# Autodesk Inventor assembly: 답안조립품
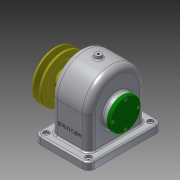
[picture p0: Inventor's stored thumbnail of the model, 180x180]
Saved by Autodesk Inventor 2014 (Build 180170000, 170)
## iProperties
Created: 2016-10
Part Number: 답안조립품
Document SubType Name: Assembly
Designer: user
Author: user
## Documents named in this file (15)
- C:\Users\user\Desktop\461008V1003\답안조립품.iam
- C:\Users\user\Desktop\461008V1003\본체.ipt
- C:\Users\user\Desktop\461008V1003\앞커버.ipt
- C:\Users\user\Desktop\461008V1003\뒤커버.ipt
- C:\Users\user\Desktop\461008V1003\볼트 M3 x 8.ipt
- C:\Users\user\Desktop\461008V1003\볼트 M3 x 10.ipt
- C:\Users\user\Desktop\461008V1003\베어링 6203.ipt
- C:\Users\user\Desktop\461008V1003\축.ipt
- C:\Users\user\Desktop\461008V1003\키 - 6 x 6 x 22.ipt
- C:\Users\user\Desktop\461008V1003\키 - 5 x 5 x 18.ipt
- C:\Users\user\Desktop\461008V1003\오일씰 28 40 8.ipt
- C:\Users\user\Desktop\461008V1003\스퍼기어.ipt
- C:\Users\user\Desktop\461008V1003\V-벨트풀리.ipt
- C:\Users\user\Desktop\461008V1003\멈춤나사 - M4x10.ipt
- C:\Users\user\Desktop\461008V1003\부시.ipt
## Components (9 placed, 3 different names)
1. V-벨트풀리:1
2. ISO 4762 M3 x 8:1
3. ISO 4762 M3 x 8:2
4. ISO 4762 M3 x 8:3
5. ISO 4762 M3 x 8:4
6. ISO 4762 M3 x 10:1
7. ISO 4762 M3 x 10:2
8. ISO 4762 M3 x 10:3
9. ISO 4762 M3 x 10:4
